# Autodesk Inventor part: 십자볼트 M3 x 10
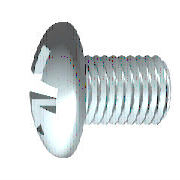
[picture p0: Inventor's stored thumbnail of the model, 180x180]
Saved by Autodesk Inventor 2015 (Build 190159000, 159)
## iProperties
IsCustomPart: 0
Created: 2012-02
Part Number: 십자볼트 M3 x 10
Material: 스테인리스강
Description: 십자 오목 머리 나사
Document SubType Name: Modeling
Standard: KS B 1023
Designer: mduedu
Standards Organization: KS
Language: ko-KR
Size Designation: A  M 3 x 10 - H
Categories: <MemberInstance><Categories><Category DisplayName="조임쇠" InternalName="e4da775c-781d-43d5-af7c-5136215cf5a6" Mnemonic="FSTN"><Category DisplayName="볼트" InternalN
Density: 1 g/cm^3
Appearance: 반광택
Author: mduedu
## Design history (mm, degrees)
workplane "Work Plane3"
sketch "스케치2"
  geometry: L1 (-3.72, 0)-(3.72, 0) reference; L2 (0, -3.72)-(0, 3.72) reference; L3 (0, 1.5)-(0, 0); L4 (0, 0)-(1.5, 0); L5 (0, 0)-(1.879, 1.879); L6 (0.253, 1.479)-(0.261, 0.456); L7 (1.479, 0.253)-(0.456, 0.261); L8 (0.253, -1.479)-(0.261, -0.456); L9 (1.479, -0.253)-(0.456, -0.261); L10 (-0.253, 1.479)-(-0.261, 0.456); L11 (-1.479, 0.253)-(-0.456, 0.261); L12 (-1.479, -0.253)-(-0.456, -0.261); L13 (-0.253, -1.479)-(-0.261, -0.456); A1 r 0.45 centre (0, 0) between (0.45, 0) and (0, 0.45); A2 r 1.5 centre (0, 0) between (1.5, 0) and (1.479, 0.253); A3 r 1.5 centre (0, 0) between (0.253, 1.479) and (0, 1.5); A4 r 1.5 centre (0, 0) between (1.479, 0.253) and (0.253, 1.479); A5 r 1.5 centre (0, 0) between (0, -1.5) and (0.253, -1.479); A6 r 1.5 centre (0, 0) between (0.253, -1.479) and (1.479, -0.253); A7 r 1.5 centre (0, 0) between (1.479, -0.253) and (1.5, 0); A8 r 1.5 centre (0, 0) between (-1.479, 0.253) and (-1.5, 0); A9 r 1.5 centre (0, 0) between (-0.253, 1.479) and (-1.479, 0.253); A10 r 1.5 centre (0, 0) between (0, 1.5) and (-0.253, 1.479); A11 r 1.5 centre (0, 0) between (-1.5, 0) and (-1.479, -0.253); A12 r 1.5 centre (0, 0) between (-1.479, -0.253) and (-0.253, -1.479); A13 r 1.5 centre (0, 0) between (-0.253, -1.479) and (0, -1.5); A14 r 0.525 centre (0, 0) between (0.525, 0) and (0, 0.525); A15 r 0.197 centre (0.457, 0.457) between (0.261, 0.456) and (0.456, 0.261); A16 r 0.197 centre (0.457, -0.457) between (0.456, -0.261) and (0.261, -0.456); A17 r 0.197 centre (-0.457, 0.457) between (-0.456, 0.261) and (-0.261, 0.456); A18 r 0.197 centre (-0.457, -0.457) between (-0.261, -0.456) and (-0.456, -0.261); 1 further point
  constraints: 38 point on circle, 22 end point, 19 symmetric about line, 18 centre point, 4 coincident, 3 collinear, 3 point on line, 3 tangent, 1 perpendicular, 21 other
  dimensions: "d4" = 45 deg angle of L5 L4; "d5" = 0.9 diameter of A1 (= 0.3 x SDM); "d6" = 3 diameter of A4 (= SDM); "d7" = 0.2525 distance from line of L6.start L3 (= 0.5 x SBR); "d14" = 1.05 diameter of A14 (= 0.35 x SDM)
extrude "슬롯" join sketch "스케치2" taper "d15" = 5 deg; stored distance "d54" = 10
revolve "절단부" stored, may be unused: angle "d56" = 90 deg
revolve "본체" stored, may be unused: angle "d18" = 90 deg
workplane "Work Plane1"
body "Solid1"
sketch "스케치1"
  geometry: L1 (10, 0)-(10, 1.5); L2 (10, 1.5)-(1, 1.5); L3 (3.962, 5.08)-(3.962, 5.08); L4 (-2.4, 0)-(-2.4, 2.59); L5 (-2.2, 1.4)-(-1.036, 0.82); L6 (-1.036, 0.82)-(-0.6, 0); L7 (-0.6, 0)-(10, 0); L8 (-5.105, 0)-(12.517, 0) reference; L9 (0, -1.016)-(0, 6.096) reference; L10 (-2.2, 1.4)-(-2.4, 1.5); L11 (-1.636, 2.657)-(-2.4, 2.59); L12 (-1.636, 2.657)-(0, 2.8); L13 (0, 2.8)-(0, 1.347); L14 (0, 1.347)-(0.693, 1.347); L15 (0.693, 1.347)-(1, 1.5); L16 (1, 1.5)-(0, 1.5); A1 r 5 centre (2.6, 0) between (-1.636, 2.657) and (-2.4, 0)
  constraints: 28 end point, 5 point on line, 4 collinear, 4 point on circle, 3 parallel, 2 perpendicular, 1 centre point, 1 horizontal, 1 tangent
  dimensions: "d1" = 3 diameter of L2 L7 (= GD); "d2" = 1.8 distance from line of L6.end L4 (= STI); "d11" = 3 diameter of L10.end L7 (= SDM); "d12" = 62 deg angle of L6 L7; "d13" = 26.5 deg angle of L5 L7; "d17" = 5.6 diameter of L12.end L7 (= KOD); "d19" = 5 deg angle of L12 L7 (= KEWI); "d20" = 2.4 distance between parallel lines of L4 L13 (= KOH); "d21" = 5 radius of A1 (= KR); "d23" = 2.6935 diameter of L14 L7 (= BDM); "d24" = 9 distance of L1.end L2.end (= GEL); "d25" = 0.30673 horizontal distance of L14.end L2.end (= GAL); "d28" = 10 distance between parallel lines of L1 L13 (= NLG)
fillet "모깎기1" dims "d29" = 1.2 (= RR)
fillet "모깎기2" dims "d16" = 0.101 (= 0.2 x SBR)
feature "스레드" dims "d8" = 9 (= GEL), "d9" = 0
chamfer "모따기1" distance "d26" = 0.30673 (= -0.5 x SPD + 0.5 x GD); stored, may be unused: second distance "d27" = 0.30683 (computed from GUL), angle "d78" = 45 deg
other parameters: "GD" = 3 (= NND) [user parameter; used in 2 equation terms], "NLG" = 10 [user parameter; used in 1 equation term], "GEL" = 9 [user parameter; used in 2 equation terms], "KOD" = 5.6 [user parameter; used in 1 equation term], "KOH" = 2.4 [user parameter; used in 2 equation terms], "SDM" = 3 [user parameter; used in 4 equation terms], "STI" = 1.8 [user parameter; used in 1 equation term], "SBR" = 0.505 [user parameter; used in 2 equation terms], "GAL" = 0.30673 (= 0.61345 x PTC) [user parameter; used in 1 equation term], "SPD" = 2.38655 (= NND - 1.2269 x PTC) [user parameter; used in 1 equation term], "KEWI" = 5 deg [user parameter; used in 1 equation term], "d3" = -2.4 (= -KOH), "d10" = 0, "KR" = 5 [user parameter; used in 1 equation term], "BDM" = 2.6935 [user parameter; used in 1 equation term], "GUL" = 0.30673 (= 0.61345 x PTC) [user parameter; used in 1 equation term], "RR" = 1.2 [user parameter; used in 1 equation term], "d79" = 0, "d80" = 0, "PTC" = 0.5 [user parameter; used in 5 equation terms], "THREADDIA" = 3 [user parameter; used in 1 equation term], "TOA" = 30 deg [user parameter], "NND" = 3 [user parameter; used in 2 equation terms], "GD1" = 2.38655 (= THREADDIA - 1.2269 x PTC) [user parameter]
